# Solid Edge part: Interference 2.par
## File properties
Last saved by: Ilambrescu
Revision: 59
Accuracy: 0.990
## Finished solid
Body 1: solid body, 5 faces, 7 edges, 4 vertices.
  Faces by surface: plane 3, cylinder 2
  Edges by curve: circle 5, line 2
Bounding box of the edges (mm): 4.000 x 4.000 x 4.000, from (-2, -7.068, 6) to (2, -3.068, 10).
Cylindrical faces by radius (mm): R2 x2
Planar faces by outward normal: +z 2, -z 1
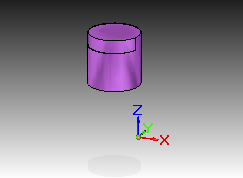
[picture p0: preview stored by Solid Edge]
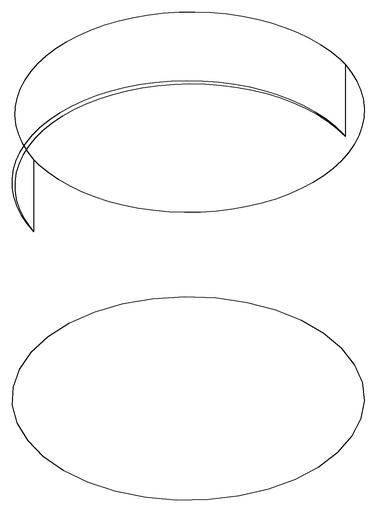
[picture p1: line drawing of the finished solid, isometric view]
